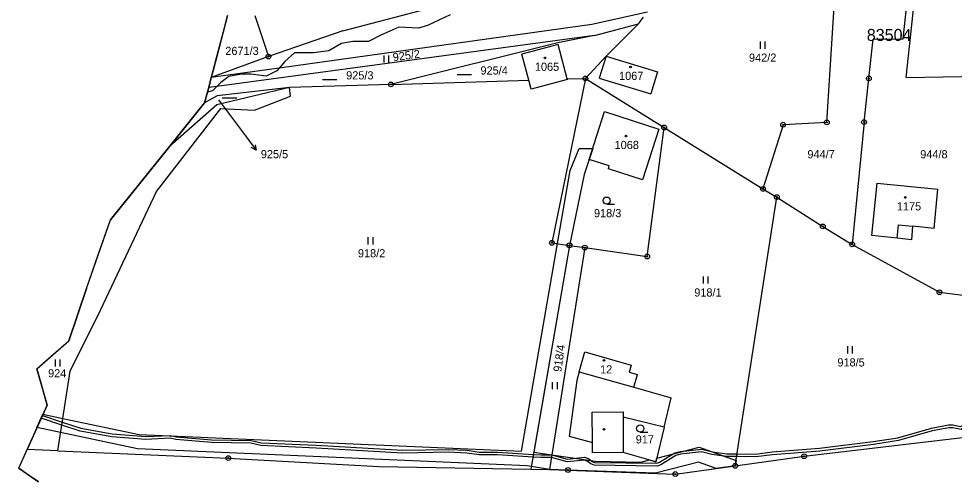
# Model space of a CAD drawing. Extents: x -439246 to -433691, y -1130252 to -1121148.
# Drawn here: x -438654.3 to -438459.6, y -1124392.3 to -1124296.8 of the extents above; entities that cross this region are included whole.
import ezdxf

# ---------------------------------------------------------------- set-up
doc = ezdxf.new("R2010")
doc.units = 0
for name, color, linetype in [('Vrstva 1', 7, 'Continuous'), ('Vrstva 13', 7, 'Continuous'), ('Vrstva 16', 7, 'Continuous'), ('Vrstva 18', 7, 'Continuous'), ('Vrstva 19', 7, 'Continuous'), ('Vrstva 24', 7, 'Continuous'), ('Vrstva 25', 7, 'Continuous'), ('Vrstva 3', 7, 'Continuous'), ('Vrstva 30', 7, 'Continuous'), ('Vrstva 37', 7, 'Continuous'), ('Vrstva 4', 7, 'Continuous'), ('Vrstva 52', 7, 'Continuous'), ('Vrstva 53', 7, 'Continuous')]:
    doc.layers.add(name, color=color, linetype=linetype)

msp = doc.modelspace()

# ---------------------------------------------------------------- linework, layer by layer
at = {"layer": 'Vrstva 1'}
for points in [[(-438469.62, -1124309.07), (-438466.08, -1124276.04)], [(-438476.52, -1124301.09), (-438470.28, -1124301.02), (-438467.64, -1124276.54)], [(-438586.86, -1124299.29), (-438520.57, -1124281.88)], [(-438486.14, -1124318.4), (-438484.5, -1124292.06)], [(-438523.49, -1124295.46), (-438535.02, -1124298)], [(-438605.16, -1124296.13), (-438602.35, -1124304.68)], [(-438525.37, -1124297.88), (-438524.3, -1124296.5)], [(-438586.86, -1124299.29), (-438602.35, -1124304.68)], [(-438535.02, -1124298), (-438600.1, -1124307.09)], [(-438534.49, -1124300.29), (-438525.37, -1124297.88)], [(-438532.1, -1124304.6), (-438525.37, -1124297.88)], [(-438534.49, -1124300.29), (-438613.05, -1124310.89)], [(-438534.49, -1124300.29), (-438542.13, -1124301.84)], [(-438477.39, -1124309.23), (-438476.52, -1124301.09)], [(-438542.13, -1124301.84), (-438576.86, -1124310.48)], [(-438542.08, -1124302.2), (-438549.59, -1124304.21)], [(-438540.17, -1124309.35), (-438542.08, -1124302.2)], [(-438602.35, -1124304.68), (-438614.25, -1124309.07)], [(-438548.15, -1124309.59), (-438549.59, -1124304.21)], [(-438536.39, -1124309.23), (-438532.1, -1124304.6)], [(-438532.1, -1124304.6), (-438533.5, -1124309.18)], [(-438532.1, -1124304.6), (-438521.39, -1124307.87)], [(-438600.1, -1124307.09), (-438614.25, -1124309.07)], [(-438536.39, -1124309.23), (-438543.36, -1124343.46)], [(-438540.17, -1124309.35), (-438536.39, -1124309.23)], [(-438540.13, -1124309.49), (-438540.17, -1124309.35)], [(-438536.39, -1124309.23), (-438519.99, -1124319.45)], [(-438533.5, -1124309.18), (-438522.79, -1124312.46)], [(-438521.39, -1124307.87), (-438522.79, -1124312.46)], [(-438478.4, -1124318.33), (-438477.39, -1124309.23)], [(-438469.62, -1124309.07), (-438454.27, -1124308.74)], [(-438613.05, -1124310.89), (-438614.78, -1124311.12)], [(-438597.95, -1124311.13), (-438613.11, -1124314.75)], [(-438597.95, -1124311.13), (-438612.99, -1124312.84)], [(-438576.86, -1124310.48), (-438597.95, -1124311.13)], [(-438597.72, -1124312.9), (-438597.95, -1124311.13)], [(-438576.86, -1124310.48), (-438548.15, -1124309.59)], [(-438547.64, -1124311.5), (-438548.15, -1124309.59)], [(-438540.13, -1124309.49), (-438547.64, -1124311.5)], [(-438612.99, -1124312.84), (-438615.62, -1124314.33)], [(-438605.22, -1124315.85), (-438597.72, -1124312.9)], [(-438613.11, -1124314.75), (-438622.86, -1124323.31)], [(-438625.62, -1124332.8), (-438612.27, -1124315.49)], [(-438612.27, -1124315.49), (-438605.22, -1124315.85)], [(-438535.57, -1124326.13), (-438532.39, -1124316.15)], [(-438532.39, -1124316.15), (-438521.1, -1124319.81)], [(-438495.25, -1124318.87), (-438499.44, -1124332.25)], [(-438486.14, -1124318.4), (-438495.25, -1124318.87)], [(-438478.4, -1124318.33), (-438480.86, -1124343.8)], [(-438521.1, -1124319.81), (-438524.5, -1124330.33)], [(-438523.52, -1124346.32), (-438519.99, -1124319.45)], [(-438519.99, -1124319.45), (-438499.44, -1124332.25)], [(-438531.42, -1124327.46), (-438535.57, -1124326.13)], [(-438531.61, -1124328.03), (-438531.42, -1124327.46)], [(-438524.5, -1124330.33), (-438531.61, -1124328.03)], [(-438499.44, -1124332.25), (-438496.56, -1124333.94)], [(-438476.76, -1124341.97), (-438475.64, -1124331.04)], [(-438475.64, -1124331.04), (-438463.04, -1124332.3)], [(-438463.81, -1124340.48), (-438463.04, -1124332.3)], [(-438637.26, -1124357.5), (-438625.62, -1124332.8)], [(-438505.21, -1124389.9), (-438496.56, -1124333.94)], [(-438496.56, -1124333.94), (-438486.97, -1124340.05)], [(-438486.97, -1124340.05), (-438480.86, -1124343.8)], [(-438468.3, -1124340.03), (-438468.56, -1124342.81)], [(-438463.81, -1124340.48), (-438468.3, -1124340.03)], [(-438471.53, -1124342.5), (-438476.76, -1124341.97)], [(-438539.7, -1124343.99), (-438547.72, -1124390.62)], [(-438543.36, -1124343.46), (-438539.7, -1124343.99)], [(-438539.7, -1124343.99), (-438536.51, -1124344.45)], [(-438480.86, -1124343.8), (-438462.72, -1124353.76)], [(-438468.56, -1124342.81), (-438471.53, -1124342.5)], [(-438536.51, -1124344.45), (-438543.85, -1124390.69)], [(-438536.51, -1124344.45), (-438523.52, -1124346.32)], [(-438462.72, -1124353.76), (-438451.84, -1124355.13)], [(-438643.61, -1124370.16), (-438637.26, -1124357.5)], [(-438537.65, -1124370.33), (-438536.48, -1124366.18)], [(-438536.48, -1124366.18), (-438526.84, -1124368.91)], [(-438526.84, -1124368.91), (-438527.27, -1124370.41)], [(-438646.16, -1124386.76), (-438643.61, -1124370.16)], [(-438537.65, -1124370.33), (-438538.15, -1124372.1)], [(-438527.27, -1124370.41), (-438525.54, -1124370.9)], [(-438526.29, -1124373.55), (-438525.54, -1124370.9)], [(-438538.15, -1124372.1), (-438539.77, -1124383.74)], [(-438526.29, -1124373.55), (-438518.54, -1124375.75)], [(-438519.99, -1124381.84), (-438518.54, -1124375.75)], [(-438519.99, -1124381.84), (-438528.54, -1124379.8)], [(-438528.54, -1124379.8), (-438528.54, -1124387.14)], [(-438519.99, -1124381.84), (-438521.71, -1124389.04)], [(-438539.77, -1124383.74), (-438534.92, -1124385.05)], [(-438534.9, -1124387.2), (-438534.92, -1124385.05)], [(-438490.87, -1124387.9), (-438457.93, -1124384)], [(-438646.16, -1124386.76), (-438652.54, -1124386.48)], [(-438646.16, -1124386.76), (-438610.69, -1124388.29)], [(-438528.54, -1124387.14), (-438534.9, -1124387.2)], [(-438521.71, -1124389.04), (-438528.54, -1124387.14)], [(-438610.69, -1124388.29), (-438579.35, -1124390.02)], [(-438505.21, -1124389.9), (-438490.87, -1124387.9)], [(-438579.35, -1124390.02), (-438547.72, -1124390.62)], [(-438547.72, -1124390.62), (-438543.85, -1124390.69)], [(-438543.85, -1124390.69), (-438540.01, -1124390.77)], [(-438540.01, -1124390.77), (-438517.68, -1124391.61)], [(-438517.68, -1124391.61), (-438505.21, -1124389.9)]]:
    msp.add_lwpolyline(points, dxfattribs=at)
at = {"layer": 'Vrstva 13'}
for points in [[(-438610.86, -1124296.13), (-438613.09, -1124304.65)], [(-438613.09, -1124304.65), (-438613.85, -1124307.55)], [(-438614.25, -1124309.07), (-438614.78, -1124311.12)], [(-438613.85, -1124307.55), (-438614.25, -1124309.07)], [(-438614.78, -1124311.12), (-438615.03, -1124312.06)], [(-438615.03, -1124312.06), (-438615.62, -1124314.33)], [(-438615.62, -1124314.33), (-438622.86, -1124323.31)], [(-438622.86, -1124323.31), (-438635.24, -1124338.68)], [(-438640.17, -1124352.96), (-438635.24, -1124338.68)], [(-438640.17, -1124352.96), (-438643.87, -1124363.89)], [(-438650.51, -1124369.67), (-438643.87, -1124363.89)], [(-438650.51, -1124369.67), (-438648.41, -1124377.26)], [(-438648.41, -1124377.26), (-438652.54, -1124386.48)], [(-438654.31, -1124390.42), (-438652.54, -1124386.48)], [(-438654.31, -1124390.42), (-438650.2, -1124393.22)]]:
    msp.add_lwpolyline(points, dxfattribs=at)
at = {"layer": 'Vrstva 16'}
msp.add_line((-438606.73, -1124321.75), (-438604.93, -1124324.15), dxfattribs=at)
for points in [[(-438612.77, -1124313.66), (-438606.73, -1124321.75)], [(-438605.13, -1124323.05), (-438604.93, -1124324.15), (-438605.93, -1124323.65)]]:
    msp.add_lwpolyline(points, dxfattribs=at)
at = {"layer": 'Vrstva 24'}
for centre, radius in [((-438602.35, -1124304.68), 0.5), ((-438602.35, -1124304.68), 0.1), ((-438536.39, -1124309.23), 0.5), ((-438536.39, -1124309.23), 0.1), ((-438477.39, -1124309.23), 0.5), ((-438477.39, -1124309.23), 0.1), ((-438576.86, -1124310.48), 0.5), ((-438576.86, -1124310.48), 0.1), ((-438519.99, -1124319.45), 0.5), ((-438495.25, -1124318.87), 0.5), ((-438495.25, -1124318.87), 0.1), ((-438486.14, -1124318.4), 0.5), ((-438486.14, -1124318.4), 0.1), ((-438478.4, -1124318.33), 0.5), ((-438478.4, -1124318.33), 0.1), ((-438519.99, -1124319.45), 0.1), ((-438499.44, -1124332.25), 0.5), ((-438499.44, -1124332.25), 0.1), ((-438496.56, -1124333.94), 0.5), ((-438496.56, -1124333.94), 0.1), ((-438486.97, -1124340.05), 0.5), ((-438486.97, -1124340.05), 0.1), ((-438543.36, -1124343.46), 0.5), ((-438543.36, -1124343.46), 0.1), ((-438539.7, -1124343.99), 0.5), ((-438539.7, -1124343.99), 0.1), ((-438536.51, -1124344.45), 0.5), ((-438536.51, -1124344.45), 0.1), ((-438480.86, -1124343.8), 0.5), ((-438480.86, -1124343.8), 0.1), ((-438523.52, -1124346.32), 0.5), ((-438523.52, -1124346.32), 0.1), ((-438462.72, -1124353.76), 0.5), ((-438462.72, -1124353.76), 0.1), ((-438610.69, -1124388.29), 0.5), ((-438610.69, -1124388.29), 0.1), ((-438490.87, -1124387.9), 0.5), ((-438490.87, -1124387.9), 0.1), ((-438540.01, -1124390.77), 0.5), ((-438540.01, -1124390.77), 0.1), ((-438517.68, -1124391.61), 0.5), ((-438505.21, -1124389.9), 0.5), ((-438505.21, -1124389.9), 0.1), ((-438517.68, -1124391.61), 0.1)]:
    msp.add_circle(centre, radius, dxfattribs=at)
at = {"layer": 'Vrstva 25'}
for p, q in [((-438499.98, -1124303.05), (-438499.98, -1124301.55)), ((-438498.98, -1124303.05), (-438498.98, -1124301.55)), ((-438578.27, -1124305.95), (-438578.27, -1124304.45)), ((-438577.27, -1124305.95), (-438577.27, -1124304.45)), ((-438563.08, -1124308.42), (-438560.08, -1124308.42)), ((-438591.12, -1124309.44), (-438588.12, -1124309.44)), ((-438611.95, -1124313.28), (-438608.95, -1124313.28)), ((-438531.96, -1124335.43), (-438530.36, -1124335.43)), ((-438581.57, -1124343.79), (-438581.57, -1124342.29)), ((-438580.57, -1124343.79), (-438580.57, -1124342.29)), ((-438511.82, -1124351.95), (-438511.82, -1124350.45)), ((-438510.82, -1124351.95), (-438510.82, -1124350.45)), ((-438481.8, -1124366.51), (-438481.8, -1124365.01)), ((-438480.8, -1124366.51), (-438480.8, -1124365.01)), ((-438646.67, -1124369.24), (-438646.67, -1124367.74)), ((-438645.67, -1124369.24), (-438645.67, -1124367.74)), ((-438543.22, -1124373.95), (-438543.22, -1124372.45)), ((-438542.22, -1124373.95), (-438542.22, -1124372.45)), ((-438524.98, -1124382.88), (-438523.38, -1124382.88))]:
    msp.add_line(p, q, dxfattribs=at)
for centre, radius in [((-438544.8, -1124304.95), 0.175), ((-438527, -1124306.84), 0.175), ((-438527.93, -1124321.24), 0.175), ((-438531.96, -1124334.68), 0.75), ((-438469.81, -1124334.02), 0.175), ((-438532.52, -1124367.96), 0.175), ((-438524.98, -1124382.13), 0.75), ((-438532.52, -1124382.28), 0.175)]:
    msp.add_circle(centre, radius, dxfattribs=at)
at = {"layer": 'Vrstva 3'}
for points in [[(-438542.08, -1124302.2), (-438549.59, -1124304.21)], [(-438540.17, -1124309.35), (-438542.08, -1124302.2)], [(-438548.15, -1124309.59), (-438549.59, -1124304.21)], [(-438532.1, -1124304.6), (-438533.5, -1124309.18)], [(-438532.1, -1124304.6), (-438521.39, -1124307.87)], [(-438540.13, -1124309.49), (-438540.17, -1124309.35)], [(-438533.5, -1124309.18), (-438522.79, -1124312.46)], [(-438521.39, -1124307.87), (-438522.79, -1124312.46)], [(-438547.64, -1124311.5), (-438548.15, -1124309.59)], [(-438540.13, -1124309.49), (-438547.64, -1124311.5)], [(-438535.57, -1124326.13), (-438532.39, -1124316.15)], [(-438532.39, -1124316.15), (-438521.1, -1124319.81)], [(-438521.1, -1124319.81), (-438524.5, -1124330.33)], [(-438531.42, -1124327.46), (-438535.57, -1124326.13)], [(-438531.61, -1124328.03), (-438531.42, -1124327.46)], [(-438524.5, -1124330.33), (-438531.61, -1124328.03)], [(-438476.76, -1124341.97), (-438475.64, -1124331.04)], [(-438475.64, -1124331.04), (-438463.04, -1124332.3)], [(-438463.81, -1124340.48), (-438463.04, -1124332.3)], [(-438471.53, -1124342.5), (-438471.25, -1124339.73)], [(-438471.25, -1124339.73), (-438468.3, -1124340.03)], [(-438463.81, -1124340.48), (-438468.3, -1124340.03)], [(-438471.53, -1124342.5), (-438476.76, -1124341.97)], [(-438537.65, -1124370.33), (-438536.48, -1124366.18)], [(-438536.48, -1124366.18), (-438526.84, -1124368.91)], [(-438526.84, -1124368.91), (-438527.27, -1124370.41)], [(-438537.65, -1124370.33), (-438526.29, -1124373.55)], [(-438527.27, -1124370.41), (-438525.54, -1124370.9)], [(-438526.29, -1124373.55), (-438525.54, -1124370.9)]]:
    msp.add_lwpolyline(points, dxfattribs=at)
at = {"layer": 'Vrstva 30'}
for points in [[(-438548.48, -1124389.92), (-438629.6, -1124386.33), (-438645.58, -1124382.98), (-438650.51, -1124381.95), (-438649.26, -1124379.15), (-438645.12, -1124380.02), (-438629.22, -1124383.35), (-438549.66, -1124386.86), (-438542.18, -1124343.63), (-438539.54, -1124328.38), (-438537.66, -1124323.8), (-438534.84, -1124323.85), (-438535.57, -1124326.13), (-438536.64, -1124329.22), (-438539.7, -1124343.99), (-438547.11, -1124387.09), (-438543.36, -1124387.62), (-438534.32, -1124388.9), (-438524.87, -1124389.15), (-438523.03, -1124388.67), (-438521.71, -1124389.04), (-438521.53, -1124388.28), (-438512.69, -1124385.99), (-438505.04, -1124388.77), (-438505.21, -1124389.9), (-438509.2, -1124390.45), (-438512.83, -1124389.13), (-438521.81, -1124391.45), (-438540.01, -1124390.77), (-438543.85, -1124390.69), (-438548.48, -1124389.92)], [(-438649.39, -1124379.45), (-438645.25, -1124380.81), (-438641.41, -1124382.07), (-438634.85, -1124383.23), (-438627.88, -1124383.79), (-438622.74, -1124383.56), (-438621.52, -1124383.85), (-438614.17, -1124384.46), (-438605.91, -1124384.6), (-438603.85, -1124385.09), (-438592.4, -1124385.61), (-438574.4, -1124386.66), (-438564.88, -1124386.48), (-438561.01, -1124386.63), (-438558.47, -1124387.03), (-438554.69, -1124387.04), (-438547.18, -1124387.51), (-438545.67, -1124387.6), (-438543.36, -1124387.6), (-438540.15, -1124388.48), (-438536.54, -1124388.13), (-438535.72, -1124388.38), (-438534.95, -1124389), (-438534.47, -1124389.19), (-438521.53, -1124389.36), (-438520.94, -1124389.14), (-438517.79, -1124387.19), (-438516.69, -1124386.9), (-438512.19, -1124386.4), (-438509.96, -1124386.96), (-438506.96, -1124387.37), (-438504.82, -1124387.39), (-438504.92, -1124387.99), (-438507, -1124387.97), (-438510.08, -1124387.54), (-438512.23, -1124387), (-438516.58, -1124387.5), (-438517.55, -1124387.75), (-438520.68, -1124389.68), (-438521.43, -1124389.96), (-438534.59, -1124389.79), (-438535.25, -1124389.52), (-438536, -1124388.92), (-438536.6, -1124388.73), (-438540.21, -1124389.08), (-438543.45, -1124388.2), (-438545.69, -1124388.2), (-438547.29, -1124388.1), (-438554.71, -1124387.64), (-438558.51, -1124387.63), (-438561.07, -1124387.23), (-438564.88, -1124387.08), (-438574.42, -1124387.26), (-438592.44, -1124386.21), (-438603.93, -1124385.69), (-438605.99, -1124385.2), (-438614.21, -1124385.06), (-438621.62, -1124384.45), (-438622.8, -1124384.16), (-438627.89, -1124384.39), (-438634.93, -1124383.83), (-438641.55, -1124382.65), (-438645.34, -1124381.4), (-438649.63, -1124379.99), (-438649.39, -1124379.45)], [(-438504.82, -1124387.39), (-438500.96, -1124387.44), (-438497.53, -1124386.98), (-438487.69, -1124386.23), (-438476.49, -1124384.86), (-438471.35, -1124384.07), (-438464.34, -1124382.04), (-438460.83, -1124381.36), (-438459.9, -1124381.37), (-438458.32, -1124381.68), (-438457.6, -1124381.27), (-438457.69, -1124382.02), (-438458.22, -1124382.32), (-438459.96, -1124381.97), (-438460.77, -1124381.96), (-438464.2, -1124382.62), (-438471.22, -1124384.65), (-438476.41, -1124385.46), (-438487.63, -1124386.83), (-438497.47, -1124387.58), (-438500.92, -1124388.04), (-438504.92, -1124387.99), (-438504.82, -1124387.39)]]:
    msp.add_lwpolyline(points, dxfattribs=at)
at = {"layer": 'Vrstva 37'}
for centre in [(-438544.8, -1124304.95), (-438527, -1124306.84), (-438527.93, -1124321.24), (-438469.81, -1124334.02), (-438532.52, -1124367.96)]:
    msp.add_circle(centre, 0.175, dxfattribs=at)
at = {"layer": 'Vrstva 4'}
for points in [[(-438564.53, -1124296.01), (-438569.26, -1124298.21)], [(-438575.24, -1124298.55), (-438578.95, -1124300.24)], [(-438571.14, -1124298.79), (-438575.24, -1124298.55)], [(-438569.26, -1124298.21), (-438571.14, -1124298.79)], [(-438584.77, -1124301.57), (-438587.15, -1124301.96)], [(-438581.55, -1124301.57), (-438584.77, -1124301.57)], [(-438578.95, -1124300.24), (-438581.55, -1124301.57)], [(-438589.78, -1124303.5), (-438592.96, -1124303.88)], [(-438587.15, -1124301.96), (-438589.78, -1124303.5)], [(-438596.95, -1124303.88), (-438598.94, -1124305.74)], [(-438592.96, -1124303.88), (-438596.95, -1124303.88)], [(-438600.1, -1124307.09), (-438600.59, -1124307.66)], [(-438598.94, -1124305.74), (-438600.1, -1124307.09)], [(-438610.6, -1124308.85), (-438612.22, -1124310.06)], [(-438607.97, -1124308.36), (-438610.6, -1124308.85)], [(-438606.01, -1124308.36), (-438607.97, -1124308.36)], [(-438602.83, -1124308.78), (-438606.01, -1124308.36)], [(-438600.59, -1124307.66), (-438602.83, -1124308.78)], [(-438613.05, -1124310.89), (-438614, -1124311.83)], [(-438612.22, -1124310.06), (-438613.05, -1124310.89)], [(-438614, -1124311.83), (-438615.03, -1124312.06)], [(-438471.53, -1124342.5), (-438471.25, -1124339.73)], [(-438471.25, -1124339.73), (-438468.3, -1124340.03)], [(-438537.65, -1124370.33), (-438526.29, -1124373.55)], [(-438534.98, -1124378.73), (-438528.54, -1124378.68)], [(-438534.92, -1124385.05), (-438534.98, -1124378.73)], [(-438528.54, -1124378.68), (-438528.54, -1124379.8)]]:
    msp.add_lwpolyline(points, dxfattribs=at)
at = {"layer": 'Vrstva 52'}
msp.add_lwpolyline([(-438650.2, -1124393.22), (-438652.74, -1124391.49), (-438654.31, -1124390.42), (-438652.54, -1124386.48), (-438651.51, -1124384.18), (-438648.41, -1124377.26), (-438649.31, -1124374), (-438650.51, -1124369.67), (-438648.65, -1124368.05), (-438643.87, -1124363.89), (-438640.17, -1124352.96), (-438637.69, -1124345.79), (-438635.24, -1124338.68), (-438634.96, -1124338.34), (-438622.86, -1124323.31), (-438615.62, -1124314.33), (-438615.03, -1124312.06), (-438614.78, -1124311.12), (-438614.25, -1124309.07), (-438614.05, -1124308.33), (-438613.85, -1124307.55), (-438613.09, -1124304.65), (-438611.72, -1124299.43), (-438610.86, -1124296.13)], dxfattribs=at)

# ---------------------------------------------------------------- texts
at = {"layer": 'Vrstva 16'}
msp.add_text('925/5', height=1.7, dxfattribs=at).set_placement((-438603.93, -1124325.85))
at = {"layer": 'Vrstva 18'}
for s, height, p in [('2671/3', 1.7, (-438611.32, -1124304.35)), ('942/2', 1.7, (-438502.35, -1124305.75)), ('925/4', 1.7, (-438558.22, -1124308.42)), ('925/3', 1.7, (-438586.17, -1124309.44)), ('925/5', 0.1, (-438612.96, -1124313.66)), ('944/7', 1.7, (-438490.19, -1124325.87)), ('944/8', 1.7, (-438466.71, -1124325.87)), ('918/3', 1.7, (-438534.6, -1124338.13)), ('918/2', 1.7, (-438583.72, -1124346.49)), ('918/1', 1.7, (-438513.73, -1124354.65)), ('918/5', 1.7, (-438483.95, -1124369.21)), ('924', 1.7, (-438648.2, -1124371.48)), ('917', 1.7, (-438525.92, -1124385.24))]:
    msp.add_text(s, height=height, dxfattribs=at).set_placement(p)
for s, rotation, p in [('925/2', 7.9107, (-438576.35, -1124305.69)), ('918/4', 81.8757, (-438541.41, -1124370.44))]:
    msp.add_text(s, height=1.7, rotation=rotation, dxfattribs=at).set_placement(p)
at = {"layer": 'Vrstva 19'}
for s, p in [('1065', (-438546.9, -1124307.65)), ('1067', (-438529.38, -1124309.54)), ('1068', (-438530.31, -1124323.94)), ('1175', (-438471.58, -1124336.72)), ('12', (-438533.33, -1124370.66))]:
    msp.add_text(s, height=1.7, dxfattribs=at).set_placement(p)
at = {"layer": 'Vrstva 53'}
msp.add_text('83504', height=2.5, dxfattribs=at).set_placement((-438477.83, -1124301.43))

doc.saveas('drawing.dxf')
